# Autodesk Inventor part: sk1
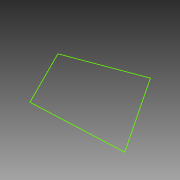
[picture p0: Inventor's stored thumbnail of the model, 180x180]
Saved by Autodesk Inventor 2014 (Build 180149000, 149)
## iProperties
Created: 2007-01
Part Number: sk1
Document SubType Name: Modeling
Designer: smithga
Density: 1 g/cm^3
Material: Generic
Appearance: Default
Author: smithga
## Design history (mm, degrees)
sketch "Sketch1"
  geometry: L1 (10.072, 30.694)-(34.274, 79.097); L2 (34.274, 79.097)-(114.354, 100.937); L3 (114.354, 100.937)-(92.129, 34.262); L4 (92.129, 34.262)-(10.072, 30.694)
  constraints: 8 end point, 1 other
